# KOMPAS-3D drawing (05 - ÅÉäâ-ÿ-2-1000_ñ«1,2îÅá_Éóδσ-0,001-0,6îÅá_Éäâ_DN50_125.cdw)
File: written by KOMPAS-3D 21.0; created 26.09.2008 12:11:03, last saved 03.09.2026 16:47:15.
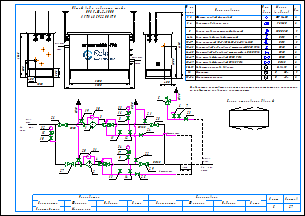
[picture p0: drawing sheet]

Sheets 1-2: A3, landscape

Document properties: Наименование: Макро:21; Автор: RaskoAdmin; Форматы листов документа: 2xA3; Полное имя файла: \\UR38nt01\Departments\КТО\КБ ПУРДГ\Заявки\Прайс-лист на типовые шкафы ГРПШ\ПРДГ_стандарт_20_03_2026\ПРДГ с РДГ(Н, В)\ПРДГ-Ш-2-1000_до1,2МПа_Рвых-0,001-0,6МПа_РДГ_DN50_125.cdw

Title block, sheet 1: Наименование: Пункт учета газа / ПУГ-Ш-400-Р / ЛГТИ.485922.001ТУ; designation: ЛГТИ.03.4411141; sheet number: 1; Количество листов документа: 2; organisation: ООО "ЭЛЬСТЕР Газэлектроника"; Форматы листов документа: A3; stored path: C:\Рабочие документы\Компас\ПУГ\Схема.cdw; Разработал: Устинов; Проверил: Кошкин; Утвердил: Кошкин
Title block, sheet 2: sheet number: 2; stored path: D:\Рабочие документы\Заявки\ПУРДГ\ПУРДГ-ШУЭО-2-100-Р 4411220.cdw; designation, second copy: ЛГТИ.03.4411141-

Views: Вид 1, Вид 2
Referenced files: wcvoit.frw
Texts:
  Normal
  № на
  схеме
  Усл.
  обозн.
  Марка
  (модель)
  Кол.
  Фильтр газовый фланцевый
  ФГ 16-50
  Регулятор давления газа
  РДГ-50
  Клапан предохранительный сбросной
  КПС DN20
  Кран шаровой газовый латунный
  DN15
  Кран кнопочный VE-РАСКО-НЗ-1,6-G1/2-М20
  Кран шаровой "под приварку" штуцерный DN20 PN16
  Кран шаровой "под приварку" штуцерный п/п DN20 PN16
  DN20
  Кран шаровой фланцевый DN50 PN16
  Кран шаровой фланцевый DN125 PN16
  DN50
  DN125
  Индикатор перепада давления
  Delta 15
  Манометр
  Манометр-напоромер
  0...     МПа
  0...     кПа
  Общий вид и габариты шкафа
  ПРДГ-Ш-2-1000
  Выход газа
  Вход газа
  Схема открывания дверей
  logo-rasko-ge.png
  Предприятие изготовитель может заменять комплектующие на аналогичные,
  не ухудшающие заявленных характеристик.
  Вход
  газа
  PDI
  Выход
  Р=     кПа
  Импульс DN20
  ≥5DN
  HYSWLongFangSong
  Р=       МПа
  Должность
  Конструктор
  Фамилия
  Подпись
  Дата
  Согласовано
  Максимкин
  Лист
  Листов
  POLYLINE_STYLE_0.18_RGB_0_0_0
  POLYLINE_STYLE_0.50_RGB_0_0_0
  POLYLINE_STYLE_0.34_RGB_0_0_0
  PHANTOM_RGB_0_0_0_SC_1_THICK_0.18
  K5LT_THIN_RGB_0_0_0_THICK_0.18
  K5LT32769_RGB_0_0_0_THICK_0.18
  K5LT12_RGB_0_0_0_SC_1_THICK_0.18
  K5LT_DASHED_RGB_0_0_0_SC_1_THICK_0.18
  ACISOTGL_RGB_0_0_0_SC_0.8_THICK_0.25
  CONTINUOUS_RGB_0_127_31_THICK_0.3
  CONTINUOUS_RGB_0_0_255_THICK_0.35
  CONTINUOUS_RGB_255_0_0_THICK_0.35
  POLYLINE_STYLE_0.25_RGB_0_0_0
  CONTINUOUS_RGB_0_0_0_THICK_0.5
  POLYLINE_STYLE_0.35_RGB_0_0_255
  CONTINUOUS_RGB_0_0_0_THICK_0.4
  CONTINUOUS_RGB_0_0_0_THICK_0.35
  Без оформления
Dimensions and other numbers on the sheet: 1; 1, 2; 2; 3, 4; 5; 6-14; 9; 15-17; 3; 18-23; 24-25; 6; 26-27; 28-29; 30-31; 32; 33-34; 400; 1050; 500; 305; 1565; 3300; 1000; 4130; 3000; 4; 10; 27; 28; 29; 23; 8; 12; 19; 20; 21; 22; 25; 24; 30; 31; 15; 16; 26; 7; 11; 14; 13; 33; 17; 34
